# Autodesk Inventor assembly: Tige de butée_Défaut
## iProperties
Shininess: 64.0
Length Units: 11269
Angle Units: 11279
Time Units: 11290
Mass Units: 11283
Length Display Precision: 3
Angle Display Precision: 2
Compacted: True
Created: 2006-11
Part Number: Tige de butée_Défaut
Document SubType Name: Assembly
Designer: profs_sti
Density: 0.0
Volumn: 0.0
Area: 0.0
PropertySet Name: Model Information
Control State: 0
Master: False
Checked Out: False
Author: profs_sti
